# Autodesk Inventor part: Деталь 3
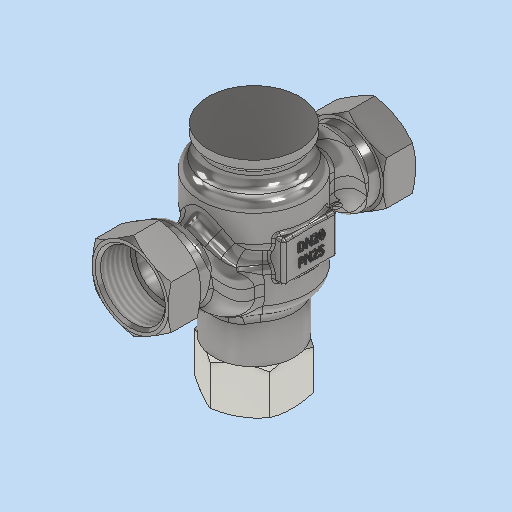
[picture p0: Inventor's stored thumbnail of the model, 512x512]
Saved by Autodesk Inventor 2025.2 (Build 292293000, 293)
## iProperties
Created: 2026-04
Part Number: Деталь 3
Material: Типовые
Document SubType Name: Modeling
Designer: igorr
Density: 1 g/cm^3
Appearance: По умолчанию
Author: igorr
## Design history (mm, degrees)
node "РабПлоскость1"
sketch "Эскиз3"
  geometry: L1 (-14.06, 8.118)-(0, 16.235); L2 (0, 16.235)-(14.06, 8.118); L3 (14.06, 8.118)-(14.06, -8.118); L4 (14.06, -8.118)-(0, -16.235); L5 (0, -16.235)-(-14.06, -8.118); L6 (-14.06, -8.118)-(-14.06, 8.118); C1 r 12.06 at (0, 0); C2 r 9.315 at (0, 0); 3 further points
  constraints: 12 end point, 3 coincident, 2 centre point, 1 horizontal alignment, 1 midpoint, 15 other
  dimensions: "d9" = 24.12 diameter of C1; "d10" = 2 dimension on C1; "d20" = 18.63 diameter of C2
extrude "Выдавливание3" new body sketch "Эскиз3" distance "d11" = 12; taper "d12" = 0 deg
sketch "Эскиз4"
  geometry: C1 r 12.06 at (0, 0) reference; C2 r 13.06 at (0, 0); C3 r 10 at (0, 0); 1 further point
  constraints: 2 centre point, 1 coincident
  dimensions: "d13" = 1 radial gap between concentric circles of C1 C2; "d14" = 20 diameter of C3
extrude "Выдавливание4" join sketch "Эскиз4" distance "d15" = 5; taper "d16" = 0 deg
sketch "Эскиз5"
  geometry: L1 (-12.06, -46)-(12.06, -46) reference; L2 (0, -46)-(0, -54.797); L3 (8.118, -46)-(16.235, -46) reference; L4 (16.235, -46)-(14.235, -46); L5 (14.235, -46)-(20.085, -42.622); L6 (20.085, -42.622)-(20.085, -46); L7 (20.085, -46)-(14.235, -46); L8 (16.235, -46)-(16.235, -34) reference; L9 (16.235, -40)-(17.87, -40); L10 (14.235, -34)-(20.085, -37.378); L11 (20.085, -37.378)-(20.085, -34); L12 (20.085, -34)-(14.235, -34); 2 further points
  constraints: 18 end point, 3 symmetric about line, 2 midpoint, 2 point on line, 1 collinear, 1 horizontal, 1 perpendicular, 1 vertical
  dimensions: "d17" = 2 distance of L3.end L4.end; "d18" = 30 deg angle of L4 L5
revolve "Вращение1" sketch "Эскиз5" stored, may be unused: angle "d19" = 90 deg
node "РабПлоскость2"
node "РабПлоскость4"
sketch "Эскиз13"
  geometry: L1 (7, 20)-(-7, 20); L2 (-15, 12)-(-15, 8); L3 (-7, 0)-(7, 0); L4 (15, 8)-(15, 12); L5 (15, 20)-(-15, 0); L6 (-15, 20)-(15, 0); A1 r 8 centre (7, 12) between (15, 12) and (7, 20); A2 r 8 centre (-7, 12) between (-7, 20) and (-15, 12); A3 r 8 centre (-7, 8) between (-15, 8) and (-7, 0); A4 r 8 centre (7, 8) between (7, 0) and (15, 8); 2 further points
  constraints: 12 end point, 8 point on circle, 8 point on line, 8 tangent, 4 centre point, 3 equal radius, 3 midpoint, 2 parallel, 1 horizontal, 1 perpendicular
  dimensions: "d60" = 30 distance of L5.start L6.start; "d61" = 20 distance of L5.end L6.start; "d62" = 8 radius of A1
feature "Лофт3" sketch "Эскиз13" dims "d63" = 0, "d64" = 90 deg, "d65" = 10, "d66" = 90 deg
  node "Ребра5"
fillet "Сопряжение11" dims "d73" = 4
mirror "Зеркальное отражение6"
mirror "Зеркальное отражение7"
sketch "Эскиз15"
  geometry: C1 r 20 at (0, 0); 1 further point
  constraints: 1 centre point, 1 coincident
  dimensions: "d74" = 40 diameter of C1
extrude "Выдавливание9" join sketch "Эскиз15" distance "d75" = 20; taper "d76" = 0 deg
fillet "Сопряжение12" dims "d77" = 5
sketch "Эскиз16"
  geometry: C1 r 20 at (0, 0); 1 further point
  constraints: 1 centre point, 1 coincident
  dimensions: "d78" = 40 diameter of C1
extrude "Выдавливание10" join sketch "Эскиз16" distance "d79" = 20; taper "d80" = 0 deg
fillet "Сопряжение13" dims "d81" = 5
feature "Комбинировать1"
  node "Твердое тело3"
fillet "Сопряжение14" dims "d82" = 4
sketch "Эскиз17"
  geometry: L1 (-7.5, 10)-(7.5, 10); L2 (7.5, 10)-(7.5, -10); L3 (7.5, -10)-(-7.5, -10); L4 (-7.5, -10)-(-7.5, 10); L5 (-7.5, 10)-(7.5, -10); L6 (7.5, 10)-(-7.5, -10); 1 further point
  constraints: 12 end point, 2 midpoint, 2 parallel, 1 horizontal, 1 perpendicular
  dimensions: "d83" = 15 distance of L1.start L1.end; "d84" = 20 distance of L1.end L2.end
extrude "Выдавливание11" join sketch "Эскиз17" distance "d85" = 21; taper "d86" = 0 deg
fillet "Сопряжение15" dims "d87" = 1
sketch "Эскиз18"
  geometry: C1 r 15 at (0, 0); 1 further point
  constraints: 1 centre point, 1 coincident
  dimensions: "d88" = 30 diameter of C1
extrude "Выдавливание12" join sketch "Эскиз18" distance "d89" = 18; taper "d90" = 0 deg
sketch "Эскиз19"
  geometry: L1 (14.06, -8.118)-(0, -16.235); L2 (0, -16.235)-(-14.06, -8.118); L3 (-14.06, -8.118)-(-14.06, 8.118); L4 (-14.06, 8.118)-(0, 16.235); L5 (0, 16.235)-(14.06, 8.118); L6 (14.06, 8.118)-(14.06, -8.118); C1 r 12.06 at (0, 0); C2 r 9.315 at (0, 0); 3 further points
  constraints: 12 end point, 3 coincident, 2 centre point, 1 horizontal alignment, 1 midpoint, 15 other
  dimensions: "d91" = 24.12 diameter of C1; "d92" = 2 dimension on C1; "d93" = 18.63 diameter of C2
extrude "Выдавливание13" join sketch "Эскиз19" distance "d94" = 17; taper "d95" = 0 deg
sketch "Эскиз20"
  geometry: C1 r 10 at (0, 0); 1 further point
  constraints: 1 centre point, 1 coincident
  dimensions: "d96" = 20 diameter of C1
extrude "Выдавливание14" cut sketch "Эскиз20" distance "d97" = 17; taper "d98" = 0 deg
sketch "Эскиз21"
  geometry: L1 (-55, -16.235)-(-55, -8.118) reference; L2 (-55, -16.235)-(-55, -14.235); L3 (-55, -14.235)-(-53.845, -16.235); L4 (-38, -16.235)-(-55, -16.235) reference; L5 (-53.845, -16.235)-(-55, -16.235); L6 (-55, 8.118)-(-55, -8.118) reference; L7 (-55, 0)-(-60.309, 0); L8 (-46.5, -16.235)-(-46.5, -19.962); L9 (-38, -16.235)-(-38, -14.235); L10 (-38, -14.235)-(-39.155, -16.235); L11 (-39.155, -16.235)-(-38, -16.235); 2 further points
  constraints: 16 end point, 2 midpoint, 2 point on line, 2 symmetric about line, 1 collinear, 1 horizontal, 1 vertical
  dimensions: "d99" = 2 distance of L1.start L2.end; "d100" = 30 deg angle of L2 L3
revolve "Вращение2" sketch "Эскиз21" stored, may be unused: angle "d101" = 360 deg
sketch "Эскиз22"
  geometry: C1 r 10 at (0, 0) reference; C2 r 15 at (0, 0); 1 further point
  constraints: 1 centre point, 1 coincident
  dimensions: "d103" = 30 diameter of C2
extrude "Выдавливание15" join sketch "Эскиз22" distance "d104" = 10; taper "d105" = 0 deg
fillet "Сопряжение16" dims "d102" = 5
sketch "Эскиз23"
  geometry: L1 (-6.1, 4.242)-(6.161, 4.242); L2 (6.161, 4.242)-(6.161, 1.13); L3 (6.161, 1.13)-(-6.1, 1.13); L4 (-6.1, 1.13)-(-6.1, 4.242); 1 further point
  constraints: 2 other
feature "Рельеф1" sketch "Эскиз23" dims "d9" = 24.12, "d17" = 2, "d18" = 30 deg, "d106" = 0.5, "d107" = 0
chamfer "Фаска1" distance "d108" = 1; stored, may be unused: second distance "d109" = 2, angle "d110" = 45 deg
sketch "Эскиз24"
  geometry: C1 r 17 at (0, 0); 1 further point
  constraints: 1 centre point, 1 coincident
  dimensions: "d111" = 34 diameter of C1
extrude "Выдавливание16" join sketch "Эскиз24" distance "d112" = 4; taper "d113" = 0 deg
fillet "Сопряжение17" dims "d114" = 1
feature "Резьба1" dims "d115" = 90, "d116" = 0
feature "Резьба2" dims "d117" = 16, "d118" = 0
feature "ʘ耀ʚ耀ʜ耀ʞ耀ʠ耀ʢ耀ʤ耀ʦ耀" dims "d8" = -46, "d9" = 24.12, "d10" = 2, "d11" = 12, "d12" = 0, "d13" = 1, "d14" = 20, "d15" = 5, "d16" = 0, "d17" = 2, "d18" = 30 deg, "d19" = 90 deg, "d20" = 18.63, "d27" = 15, "d54" = 16, "d60" = 30, "d61" = 20, "d62" = 8, "d63" = 0, "d64" = 90 deg, "d65" = 10, "d66" = 90 deg, "d73" = 4, "d74" = 40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
node "Твердое тело2"
feature "Шаблон Твердое тело2:1"
